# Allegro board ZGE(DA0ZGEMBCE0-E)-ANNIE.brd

Outline 299.69 x 178.8 mm; copper layers: TOP, SGND, IN1, SGND1, IN2, SVCC, SVCC1, IN3, SGND2, IN4, SGND3, BOTTOM. Coordinates in mm from the lower left corner of the outline.
Outline path: 0,55.5 0,51.5 arc(0.44,50.44) 1.5,50 3.2,50 arc(3.55,50.15) 3.7,50.5 3.7,50.9 arc(3.55,51.25) 3.2,51.4 2.7,51.4 arc(2.35,51.55) 2.2,51.9 2.2,53.7 arc(2.43,54.27) 3,54.5 4.9,54.5 arc(5.47,54.27) 5.7,53.7 5.7,51.81 arc(5.72,51.6) 5.78,51.41 6.32,50.19 arc(6.38,50) 6.4,49.79 6.4,39 5.5,39 arc(4.79,38.71) 4.5,38 4.5,9 arc(5.09,7.59) 6.5,7 13.9,7 arc(14.61,7.29) 14.9,8 14.9,10.9 arc(15.19,11.61) 15.9,11.9 38.9,11.9 arc(39.61,11.61) 39.9,10.9 39.9,8 arc(40.19,7.29) 40.9,7 48.9,7 arc(49.61,7.29) 49.9,8 49.9,10.9 arc(50.19,11.61) 50.9,11.9 61.4,11.9 arc(62.11,11.61) 62.4,10.9 62.4,10.4 91.4,10.4 arc(92.11,10.11) 92.4,9.4 92.4,8 arc(92.69,7.29) 93.4,7 278.2,7 arc(279.61,6.41) 280.2,5 280.2,1 arc(280.49,0.29) 281.2,0 296.2,0 arc(297.61,0.59) 298.2,2 298.2,4.85 288.65,4.85 arc(288.15,5.35) 288.65,5.85 288.65,17.55 arc(288.15,18.05) 288.65,18.55 298.2,18.55 298.2,21 299.6,21 299.6,34.7 298.2,34.7 298.2,36 299.69,36 299.69,48 298.2,48 298.2,49.25 296.2,49.25 arc(295.85,49.4) 295.7,49.75 295.7,50.05 arc(295.85,50.4) 296.2,50.55 298.2,50.55 298.2,59.5 arc(297.61,60.91) 296.2,61.5 268.9,61.5 268.9,62.5 224.4,62.5 arc(214.23,63.81) 204.73,67.67 204.73,67.67 arc(201.8,68.29) 199.04,67.12 arc(193.17,67.15) 192.31,72.95 192.42,73.12 arc(193.19,75.97) 192.21,78.75 arc(186.4,90) 184.4,102.5 184.4,174.9 arc(183.81,176.31) 182.4,176.9 131.3,176.9 131.3,177.8 arc(131.01,178.51) 130.3,178.8 105.15,178.8 105.15,176.3 arc(104.35,175.5) 103.55,176.3 103.55,178.8 95.55,178.8 95.55,168.9 arc(96.05,168.4) 95.55,167.9 78.25,167.9 arc(77.75,168.4) 78.25,168.9 78.25,178.8 70.8,178.8 70.8,170.09 arc(70.98,169.66) 70.55,169.84 55.55,169.84 arc(55.12,169.66) 55.3,170.09 55.3,178.8 52.1,178.8 52.1,177.7 41.9,177.7 41.9,176.2 9.9,176.2 9.9,177.7 6.5,177.7 arc(5.09,177.11) 4.5,175.7 4.5,57.5 arc(4.35,57.15) 4,57 1.5,57 arc(0.44,56.56) 0,55.5

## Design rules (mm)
constraint set DEFAULT: min track width 0.14
net group DFP-S3.5(4.5)W6(5)-T13B: nets M_B_DQSN8 M_B_DQSP8
net group DFP-S3.5(4.5)W6(5)-T23B: nets M_A_DQSN8 M_A_DQSP8
net group DFP-S7W5.5-T: nets VGA_XTALIN VGA_XTALOUT
net group DFP-S3.5(4.5)W6(5)-T1B: nets M_B_DQSN0 M_B_DQSN1 M_B_DQSN2 M_B_DQSN3 M_B_DQSN4 M_B_DQSN5 M_B_DQSN6 M_B_DQSN7 M_B_DQSP0 M_B_DQSP1 M_B_DQSP2 M_B_DQSP3 M_B_DQSP4 M_B_DQSP5 M_B_DQSP6 M_B_DQSP7
net group DFP-S3.5(4.5)W6(5)-T2B: nets M_A_DQSN0 M_A_DQSN1 M_A_DQSN2 M_A_DQSN3 M_A_DQSN4 M_A_DQSN5 M_A_DQSN6 M_A_DQSN7 M_A_DQSP0 M_A_DQSP1 M_A_DQSP2 M_A_DQSP3 M_A_DQSP4 M_A_DQSP5 M_A_DQSP6 M_A_DQSP7
net group DFP-S4(4.5)W4.5(3.5)-T2B: nets M_A_DIM0_CLKN0 M_A_DIM0_CLKN1 M_A_DIM0_CLKP0 M_A_DIM0_CLKP1 M_A_DIM1_CLKN0 M_A_DIM1_CLKN1 M_A_DIM1_CLKP0 M_A_DIM1_CLKP1
net group DFP-S4(4.5: nets DP_USB_MUX_SSRXN DP_USB_MUX_SSRXP DP_USB_MUX_SSTXN DP_USB_MUX_SSTXP USB30_RX1+ USB30_RX1+_C USB30_RX1- USB30_RX1-_C USB30_RX2+ USB30_RX2+_C USB30_RX2- USB30_RX2-_C USB30_RX3+ USB30_RX3+_RTO USB30_RX3- USB30_RX3-_RTO USB30_RX4+ USB30_RX4- USB30_TX1+ USB30_TX1+_C USB30_TX1- USB30_TX1-_C USB30_TX2+ USB30_TX2+_C USB30_TX2- USB30_TX2-_C USB30_TX3+ USB30_TX3+_RTI USB30_TX3- USB30_TX3-_RTI USB30_TX4+ USB30_TX4-
net group DFP-S4(4.5: nets VMA_CLK0 VMA_CLK0# VMA_CLK1 VMA_CLK1# VMA_WCK01 VMA_WCK01# VMA_WCK23 VMA_WCK23# VMA_WCK45 VMA_WCK45# VMA_WCK67 VMA_WCK67# VMA_WCKB01 VMA_WCKB01# VMA_WCKB23 VMA_WCKB23# VMA_WCKB45 VMA_WCKB45# VMA_WCKB67 VMA_WCKB67# VMB_CLK0 VMB_CLK0# VMB_CLK1 VMB_CLK1# VMB_WCK01 VMB_WCK01# VMB_WCK23 VMB_WCK23# VMB_WCK45 VMB_WCK45# VMB_WCK67 VMB_WCK67# VMB_WCKB01 VMB_WCKB01# VMB_WCKB23 VMB_WCKB23# VMB_WCKB45 VMB_WCKB45# VMB_WCKB67 VMB_WCKB67# VMC_CLK0 VMC_CLK0# VMC_CLK1 VMC_CLK1# VMC_WCK01 VMC_WCK01# VMC_WCK23 VMC_WCK23# VMC_WCK45 VMC_WCK45# VMC_WCK67 VMC_WCK67# VMC_WCKB01 VMC_WCKB01# VMC_WCKB23 VMC_WCKB23# VMC_WCKB45 VMC_WCKB45# VMC_WCKB67 VMC_WCKB67# VMD_CLK0 VMD_CLK0# VMD_CLK1 VMD_CLK1# VMD_WCK01 VMD_WCK01# VMD_WCK23 VMD_WCK23# VMD_WCK45 VMD_WCK45# VMD_WCK67 VMD_WCK67# VMD_WCKB01 VMD_WCKB01# VMD_WCKB23 VMD_WCKB23# VMD_WCKB45 VMD_WCKB45# VMD_WCKB67 VMD_WCKB67#
net group DFP-S4W4.5(3.5)-T1B: nets M_B_DIM0_CLKN0 M_B_DIM0_CLKN1 M_B_DIM0_CLKP0 M_B_DIM0_CLKP1 M_B_DIM1_CLKN0 M_B_DIM1_CLKN1 M_B_DIM1_CLKP0 M_B_DIM1_CLKP1
net group DFP-S5(3.1)W5.5(3.4)-T1: nets C_PEG_TXN0 C_PEG_TXN1 C_PEG_TXN2 C_PEG_TXN3 C_PEG_TXN4 C_PEG_TXN5 C_PEG_TXN6 C_PEG_TXN7 C_PEG_TXN8 C_PEG_TXN9 C_PEG_TXN10 C_PEG_TXN11 C_PEG_TXN12 C_PEG_TXN13 C_PEG_TXN14 C_PEG_TXN15 C_PEG_TXP0 C_PEG_TXP1 C_PEG_TXP2 C_PEG_TXP3 C_PEG_TXP4 C_PEG_TXP5 C_PEG_TXP6 C_PEG_TXP7 C_PEG_TXP8 C_PEG_TXP9 C_PEG_TXP10 C_PEG_TXP11 C_PEG_TXP12 C_PEG_TXP13 C_PEG_TXP14 C_PEG_TXP15 PEG_TXN0 PEG_TXN1 PEG_TXN2 PEG_TXN3 PEG_TXN4 PEG_TXN5 PEG_TXN6 PEG_TXN7 PEG_TXN8 PEG_TXN9 PEG_TXN10 PEG_TXN11 PEG_TXN12 PEG_TXN13 PEG_TXN14 PEG_TXN15 PEG_TXP0 PEG_TXP1 PEG_TXP2 PEG_TXP3 PEG_TXP4 PEG_TXP5 PEG_TXP6 PEG_TXP7 PEG_TXP8 PEG_TXP9 PEG_TXP10 PEG_TXP11 PEG_TXP12 PEG_TXP13 PEG_TXP14 PEG_TXP15
net group DFP-S5(3.1)W5.5(3.4)-T4: nets DMI_RXN0 DMI_RXN1 DMI_RXN2 DMI_RXN3 DMI_RXP0 DMI_RXP1 DMI_RXP2 DMI_RXP3 DMI_TXN0 DMI_TXN1 DMI_TXN2 DMI_TXN3 DMI_TXP0 DMI_TXP1 DMI_TXP2 DMI_TXP3
net group DFP-S5(3.1: nets CLK_CPU_BCLKN CLK_CPU_BCLKP CLK_DPLL_NSCCLKN CLK_DPLL_NSCCLKP CLK_PCIE_LANN CLK_PCIE_LANP CLK_PCIE_SSD1N CLK_PCIE_SSD1N_R CLK_PCIE_SSD1P CLK_PCIE_SSD1P_R CLK_PCIE_SSD2N CLK_PCIE_SSD2N_R CLK_PCIE_SSD2P CLK_PCIE_SSD2P_R CLK_PCIE_TBTN CLK_PCIE_TBTP CLK_PCIE_WLANN CLK_PCIE_WLANP CLK_VGA_N CLK_VGA_P CNV_WR_CLKN CNV_WR_CLKP CNV_WRXN0 CNV_WRXN1 CNV_WRXP0 CNV_WRXP1 CNV_WT_CLKN CNV_WT_CLKP CNV_WTXN0 CNV_WTXN1 CNV_WTXP0 CNV_WTXP1 CON_UTC_D1N CON_UTC_D1P CON_UTC_D2N CON_UTC_D2P CON_UTC_RX1N CON_UTC_RX1P CON_UTC_RX2N CON_UTC_RX2P CON_UTC_SBU1 CON_UTC_SBU2 CON_UTC_TX1N CON_UTC_TX1P CON_UTC_TX2N CON_UTC_TX2P CPU_PCI_BCLKN CPU_PCI_BCLKP DP_USB_MUX_RX1N DP_USB_MUX_RX1P DP_USB_MUX_RX2N DP_USB_MUX_RX2P DP_USB_MUX_SBU1 DP_USB_MUX_SBU2 DP_USB_MUX_TX1N DP_USB_MUX_TX1P DP_USB_MUX_TX2N DP_USB_MUX_TX2P NV_USB2_D_N NV_USB2_D_P PCIE_RXN9_SSD PCIE_RXN9_SSD_R PCIE_RXN10_SSD PCIE_RXN10_SSD_R PCIE_RXN11_SSD PCIE_RXN11_SSD_R PCIE_RXN12_SSD PCIE_RXN12_SSD_R PCIE_RXN14_LAN PCIE_RXN15_WLAN PCIE_RXN17_TBT PCIE_RXN17_TBT_C PCIE_RXN18_TBT PCIE_RXN18_TBT_C PCIE_RXN19_TBT PCIE_RXN19_TBT_C PCIE_RXN20_TBT PCIE_RXN20_TBT_C PCIE_RXN21_SSD PCIE_RXN21_SSD_R PCIE_RXN22_SSD PCIE_RXN22_SSD_R PCIE_RXN23_SSD PCIE_RXN23_SSD_R PCIE_RXN24_SSD PCIE_RXN24_SSD_R PCIE_RXP9_SSD PCIE_RXP9_SSD_R PCIE_RXP10_SSD PCIE_RXP10_SSD_R PCIE_RXP11_SSD PCIE_RXP11_SSD_R PCIE_RXP12_SSD PCIE_RXP12_SSD_R PCIE_RXP14_LAN PCIE_RXP15_WLAN PCIE_RXP17_TBT PCIE_RXP17_TBT_C PCIE_RXP18_TBT PCIE_RXP18_TBT_C PCIE_RXP19_TBT PCIE_RXP19_TBT_C PCIE_RXP20_TBT PCIE_RXP20_TBT_C PCIE_RXP21_SSD PCIE_RXP21_SSD_R PCIE_RXP22_SSD PCIE_RXP22_SSD_R PCIE_RXP23_SSD PCIE_RXP23_SSD_R PCIE_RXP24_SSD PCIE_RXP24_SSD_R PCIE_TXN9_SSD PCIE_TXN9_SSD_R PCIE_TXN10_SSD PCIE_TXN10_SSD_R PCIE_TXN11_SSD PCIE_TXN11_SSD_R PCIE_TXN12_SSD PCIE_TXN12_SSD_R PCIE_TXN14_LAN PCIE_TXN14_LAN_C PCIE_TXN15_WLAN PCIE_TXN15_WLAN_C PCIE_TXN17_TBT PCIE_TXN17_TBT_C PCIE_TXN18_TBT PCIE_TXN18_TBT_C PCIE_TXN19_TBT PCIE_TXN19_TBT_C PCIE_TXN20_TBT PCIE_TXN20_TBT_C PCIE_TXN21_SSD PCIE_TXN21_SSD_R PCIE_TXN22_SSD PCIE_TXN22_SSD_R PCIE_TXN23_SSD PCIE_TXN23_SSD_R PCIE_TXN24_SSD PCIE_TXN24_SSD_R PCIE_TXP9_SSD PCIE_TXP9_SSD_R PCIE_TXP10_SSD PCIE_TXP10_SSD_R PCIE_TXP11_SSD PCIE_TXP11_SSD_R PCIE_TXP12_SSD PCIE_TXP12_SSD_R PCIE_TXP14_LAN PCIE_TXP14_LAN_C PCIE_TXP15_WLAN PCIE_TXP15_WLAN_C PCIE_TXP17_TBT PCIE_TXP17_TBT_C PCIE_TXP18_TBT PCIE_TXP18_TBT_C PCIE_TXP19_TBT PCIE_TXP19_TBT_C PCIE_TXP20_TBT PCIE_TXP20_TBT_C PCIE_TXP21_SSD PCIE_TXP21_SSD_R PCIE_TXP22_SSD PCIE_TXP22_SSD_R PCIE_TXP23_SSD PCIE_TXP23_SSD_R PCIE_TXP24_SSD PCIE_TXP24_SSD_R SATA_RXN0 SATA_RXN0_CN SATA_RXN_IN SATA_RXN_OUT SATA_RXP0 SATA_RXP0_CN SATA_RXP_IN SATA_RXP_OUT SATA_TXN0 SATA_TXN0_CN SATA_TXN_IN SATA_TXN_OUT SATA_TXP0 SATA_TXP0_CN SATA_TXP_IN SATA_TXP_OUT TBTA_USB2_D_N TBTA_USB2_D_N_T TBTA_USB2_D_P TBTA_USB2_D_P_T USB3O2_MUX_SSTX1N USB3O2_MUX_SSTX1P USB3O2_MUX_SSTX2N USB3O2_MUX_SSTX2P USBP1+ USBP1+_C USBP1- USBP1-_C USBP2+ USBP2+_C USBP2- USBP2-_C USBP3+ USBP3+_C USBP3+_C_R USBP3- USBP3-_C USBP3-_C_R USBP4+ USBP4- USBP5+ USBP5- USBP6+ USBP6+_C USBP6- USBP6-_C USBP7+ USBP7+_R USBP7- USBP7-_R USBP8+ USBP8- USBP14+ USBP14-
net group DFP-S5W5-T1234B: nets 8816ARGDN 8816AVSNS 24780_SRN 24780_SRP FVDDQ_SENSE_I FVDDQ_SENSE_V GPU_ADC_INN GPU_ADC_INP NVVDD_SENSE_I NVVDD_SENSE_V VGPU_CORE_SENSE VSS_GPU_SENSE
net group DFP-S5W5.5(3.4: nets MBCLK1_GPU MBDATA1_GPU USB_I2C_SCL USB_I2C_SDA
net group DFP-S5W5.5-TB: nets PEG_RXN0 PEG_RXN0_C PEG_RXN1 PEG_RXN1_C PEG_RXN2 PEG_RXN2_C PEG_RXN3 PEG_RXN3_C PEG_RXN4 PEG_RXN4_C PEG_RXN5 PEG_RXN5_C PEG_RXN6 PEG_RXN6_C PEG_RXN7 PEG_RXN7_C PEG_RXN8 PEG_RXN8_C PEG_RXN9 PEG_RXN9_C PEG_RXN10 PEG_RXN10_C PEG_RXN11 PEG_RXN11_C PEG_RXN12 PEG_RXN12_C PEG_RXN13 PEG_RXN13_C PEG_RXN14 PEG_RXN14_C PEG_RXN15 PEG_RXN15_C PEG_RXP0 PEG_RXP0_C PEG_RXP1 PEG_RXP1_C PEG_RXP2 PEG_RXP2_C PEG_RXP3 PEG_RXP3_C PEG_RXP4 PEG_RXP4_C PEG_RXP5 PEG_RXP5_C PEG_RXP6 PEG_RXP6_C PEG_RXP7 PEG_RXP7_C PEG_RXP8 PEG_RXP8_C PEG_RXP9 PEG_RXP9_C PEG_RXP10 PEG_RXP10_C PEG_RXP11 PEG_RXP11_C PEG_RXP12 PEG_RXP12_C PEG_RXP13 PEG_RXP13_C PEG_RXP14 PEG_RXP14_C PEG_RXP15 PEG_RXP15_C
net group DFP-S6W30-T1234B: nets C_SPKL+ C_SPKL- F_SPKL+ F_SPKL- F_SPKR+ F_SPKR- N53217580 N53217584 N53218545 N53218614 N56482348 N56482351 N56482420 N56482438 N56545499 N56545754 N56546274 N56546363 R_SPKL+ R_SPKL- R_SPKR+ R_SPKR- S_SPKR+ S_SPKR-
net group DFP-S7(4: nets AUX_SRCN_TBT_C AUX_SRCP_TBT_C C_GPU_TBT_AUXN C_GPU_TBT_AUXP C_GPU_TBT_D0 C_GPU_TBT_D0# C_GPU_TBT_D1 C_GPU_TBT_D1# C_GPU_TBT_D2 C_GPU_TBT_D2# C_GPU_TBT_D3 C_GPU_TBT_D3# C_INT_DP_AUXN C_INT_DP_AUXP C_OUT_DP_TXN0 C_OUT_DP_TXN1 C_OUT_DP_TXN2 C_OUT_DP_TXN3 C_OUT_DP_TXP0 C_OUT_DP_TXP1 C_OUT_DP_TXP2 C_OUT_DP_TXP3 C_OUT_EDP_TXN0 C_OUT_EDP_TXN1 C_OUT_EDP_TXN2 C_OUT_EDP_TXN3 C_OUT_EDP_TXP0 C_OUT_EDP_TXP1 C_OUT_EDP_TXP2 C_OUT_EDP_TXP3 DDI1_TX0_DN DDI1_TX0_DN_C DDI1_TX0_DP DDI1_TX0_DP_C DDI1_TX1_DN DDI1_TX1_DN_C DDI1_TX1_DP DDI1_TX1_DP_C DDI1_TX2_DN DDI1_TX2_DN_C DDI1_TX2_DP DDI1_TX2_DP_C DDI1_TX3_DN DDI1_TX3_DN_C DDI1_TX3_DP DDI1_TX3_DP_C DP_D0 DP_D0# DP_D1 DP_D1# DP_D2 DP_D2# DP_D3 DP_D3# DP_TXN0_R DP_TXN1_R DP_TXN2_R DP_TXN3_R DP_TXP0_R DP_TXP1_R DP_TXP2_R DP_TXP3_R DP_USB_MUX_AUXN DP_USB_MUX_AUXP DP_USB_MUX_ML0N DP_USB_MUX_ML0P DP_USB_MUX_ML1N DP_USB_MUX_ML1P DP_USB_MUX_ML2N DP_USB_MUX_ML2P DP_USB_MUX_ML3N DP_USB_MUX_ML3P EDP_AUX#_C EDP_AUX_C EDP_TXN0_C EDP_TXN1_C EDP_TXN2_C EDP_TXN3_C EDP_TXP0_C EDP_TXP1_C EDP_TXP2_C EDP_TXP3_C GPU_TBT_AUXN GPU_TBT_AUXP GPU_TBT_D0 GPU_TBT_D0# GPU_TBT_D1 GPU_TBT_D1# GPU_TBT_D2 GPU_TBT_D2# GPU_TBT_D3 GPU_TBT_D3# IFPF_AUX+ IFPF_AUX- IFPF_L0+ IFPF_L0- IFPF_L1+ IFPF_L1- IFPF_L2+ IFPF_L2- IFPF_L3+ IFPF_L3- INT_DP_AUXN INT_DP_AUXN_Q INT_DP_AUXP INT_DP_AUXP_Q INT_EDP_AUXN INT_EDP_AUXP INT_EDP_TXN0 INT_EDP_TXN0_R INT_EDP_TXN1 INT_EDP_TXN1_R INT_EDP_TXN2 INT_EDP_TXN2_R INT_EDP_TXN3 INT_EDP_TXN3_R INT_EDP_TXP0 INT_EDP_TXP0_R INT_EDP_TXP1 INT_EDP_TXP1_R INT_EDP_TXP2 INT_EDP_TXP2_R INT_EDP_TXP3 INT_EDP_TXP3_R OUT_DP_TXN0 OUT_DP_TXN1 OUT_DP_TXN2 OUT_DP_TXN3 OUT_DP_TXP0 OUT_DP_TXP1 OUT_DP_TXP2 OUT_DP_TXP3 TBTA_AUX_N TBTA_AUX_P TBTA_DPSRC_AUX_N TBTA_DPSRC_AUX_P TBTA_LSRX TBTA_LSTX TBTA_SBU1 TBTA_SBU2
net group DFP-S7W5.5-TB: nets TBTA_CA2HD_0_N TBTA_CA2HD_0_P TBTA_CA2HD_1_N TBTA_CA2HD_1_P TBTA_HD2CA_0_N TBTA_HD2CA_0_P TBTA_HD2CA_1_N TBTA_HD2CA_1_P TBTA_TX0_N TBTA_TX0_P TBTA_TX1_N TBTA_TX1_P
net group DFP-S8(5: nets GPU_USB_L0+ GPU_USB_L0- GPU_USB_L1+ GPU_USB_L1- USB3_RT_RX1N USB3_RT_RX1P USB3_RT_SSRXN USB3_RT_SSRXP USB3_RT_SSTXN USB3_RT_SSTXP USB3_RT_TX1N USB3_RT_TX1P USB3O2_MUX_SSRXN USB3O2_MUX_SSRXP USB3O2_MUX_SSTXN USB3O2_MUX_SSTXP
net group DFP-S11(6: nets C_TX0_HDMI+ C_TX0_HDMI- C_TX1_HDMI+ C_TX1_HDMI- C_TX2_HDMI+ C_TX2_HDMI- C_TXC_HDMI+ C_TXC_HDMI- GPU_CLK GPU_CLK# GPU_CLK#_C GPU_CLK_C GPU_D0 GPU_D0# GPU_D0#_C GPU_D0_C GPU_D1 GPU_D1# GPU_D1#_C GPU_D1_C GPU_D2 GPU_D2# GPU_D2#_C GPU_D2_C TX0_HDMI+ TX0_HDMI- TX1_HDMI+ TX1_HDMI- TX2_HDMI+ TX2_HDMI- TXC_HDMI+ TXC_HDMI- USB30_RX1+_R USB30_RX1+_RT USB30_RX1-_R USB30_RX1-_RT USB30_RX2+_R USB30_RX2+_RT USB30_RX2-_R USB30_RX2-_RT USB30_RX3+_R USB30_RX3+_RTI USB30_RX3-_R USB30_RX3-_RTI USB30_TX1+_R USB30_TX1+_RT USB30_TX1-_R USB30_TX1-_RT USB30_TX2+_R USB30_TX2+_RT USB30_TX2-_R USB30_TX2-_RT USB30_TX3+_C USB30_TX3+_R USB30_TX3+_RTO USB30_TX3-_C USB30_TX3-_R USB30_TX3-_RTO
net group W4-TB: nets USB2_COMP
net group W5-T1234B: nets FB_CAL_PD_VDDQ FB_CAL_PU_GND FB_CAL_TERM_GND
net group W5.5(3.4: nets 2ND_MBCLK 2ND_MBDATA 3ND_MBCLK 3ND_MBCLK_C 3ND_MBDATA 3ND_MBDATA_C 81215_ALERT 81215_SCLK 81215_SDIO ACZ_BCLK ACZ_RST# ACZ_SDIN0_R ACZ_SDO ACZ_SYNC AUD_AZACPU_SCLK AUD_AZACPU_SCLK_R AUD_AZACPU_SDI AUD_AZACPU_SDI_R AUD_AZACPU_SDO AUD_AZACPU_SDO_R BL# BL_ON BLON_EN BLONCON CL_CLK CL_DATA CLK_PCI_EC CLK_PCI_EC_R CLK_PCI_LPC CLK_PCI_LPC_C CLK_PCI_LPC_R CLKIN_XTAL CNV_BRI_DT CNV_BRI_RSP CNV_RGI_DT CNV_RGI_RSP CPU_PLTRST# CPU_PLTRST#R DDCCLK_NOR DDCCLK_NOR-1 DDCDATA_NOR DDCDATA_NOR-1 DDR4_SUSON_2V5 DDR_DRAMRST# DDR_PG_CNTL DDR_VTTT_PG_CTRL DGPU_HOLD_RST# DGPU_OPP# DGPU_OPP#_PROCHOT# DMIC_CLK DMIC_CLK_C DMIC_DAT DMIC_DATA_C DP_HPD DP_HPD_PCH DP_HPD_PCH_R DPWROK_R EC_PECI EC_PECR_R EC_PWROK EC_PWROK_R EDP_HPD_GPU EDP_HPD_R EDP_HPD_RR EDP_VDD_EN ESPI_EC_IO0 ESPI_EC_IO1 ESPI_EC_IO2 ESPI_EC_IO3 FAN1_PWM FAN1_PWM_Q FAN1_RPM FAN2_PWM FAN2_PWM_Q FAN2_RPM FRM_LCK# FRM_LCK#_PANEL GFX_SCL GFX_SDA GPIO27_IFPC_HPD GPIO27_IFPE_HPD_Q GPU_DDCCLK GPU_DDCDATA GPU_IFPB_I2C_SCL GPU_IFPB_I2C_SDA GPU_THROTTING# GPU_USB_I2C_SCL GPU_USB_I2C_SDA GPUT_CLK GPUT_DATA H_CPU_SVIDALRT# H_CPU_SVIDDAT H_PROCHOT# H_PROCHOT#_CPU H_TCK H_TDI H_TDO H_TMS H_TRST# H_VCCST_PWRGD HDMI_HPD HDMI_HPD_DC HDMI_HPD_PCH HDMI_HPD_PCH_R HDMI_SCLK HDMI_SDATA HOLLD#_7 HP_JD#_EC HPD_IFPD HWPG HWPG_1.8VS5 HWPG_1VS5 HWPG_2.5V HWPG_VDDR I2C0_SCL I2C0_SDA I2C1_SCL I2C1_SDA I2C_TP_SCL_R I2C_TP_SDA_R IFPB_I2C_SCL IFPB_I2C_SDA IMVP_PWRGD LCD_BL_PWM LCD_BLEN LCD_VDD LID# LID#_EC_L LPC_LAD0 LPC_LAD0_C LPC_LAD1 LPC_LAD1_C LPC_LAD2 LPC_LAD2_C LPC_LAD3 LPC_LAD3_C LPC_LFRAME# LPC_LFRAME#_C MAINON MB_THRMTRIP# MBCLK MBDATA MODEM_CLKREQ N17086720 N49317148 N53212868 N53212870 N53213208 N53256180 N53256182 N56382763 N56382839 NGFF1_RST# NGFF2_RST# PCH_AZ_CODEC_BITCLK PCH_AZ_CODEC_RST# PCH_AZ_CODEC_SDIN0 PCH_AZ_CODEC_SDOUT PCH_AZ_CODEC_SYNC PCH_BRIGHT PCH_PECI PCH_PWROK PCH_RSMRST# PCH_SMBCLK PCH_SMBDATA PCH_SPI1_CLK PCH_SPI1_CLK_L PCH_SPI1_SI PCH_SPI1_SI_L PCH_SPI1_SO PCH_SPI1_SO_L PCH_SPI_CLK_EC PCH_SPI_CS0# PCH_SPI_IO2 PCH_SPI_IO3 PCH_SPI_SI_EC PCH_SPI_SO_EC PCI_PLTRST# PCIE_CLKREQ_LAN# PCIE_CLKREQ_NGFF1# PCIE_CLKREQ_NGFF2# PCIE_CLKREQ_TBT# PCIE_CLKREQ_TBT#_C PCIE_CLKREQ_VGA# PCIE_CLKREQ_WLAN# PECI PEGX_RST# PEX_CLKREQ PLTRST# PLTRST#_EC PM_THRMTRIP# PM_THRMTRIP#_L PPC_I2CM_SCL_C PPC_I2CM_SDA_C PPC_I2CS_SCL_C PPC_I2CS_SDA_C PROCHOT_EC PROCPWRGD ROM_CS ROM_CS_R ROM_SCLK ROM_SCLK_R ROM_SI ROM_SI_R ROM_SO RSMRST# RTC_RST# S5_ON SLP_A# SLP_A#_L SLP_S3#_L SLP_S4#_L SMB_ME1_CLK SMB_ME1_DAT SMB_PCH_CLK SMB_PCH_DAT SPI1_IO2 SPI1_IO3 SPI_CS0#_UR_ME SPI_TPM_CS# SPI_TPM_CS#_L SRTC_RST# SUSB# SUSC# SUSON SYS_HWPG SYS_PWROK TBT_EE_CLK TBT_EE_CS_N TBT_EE_DI TBT_EE_DO TBT_EE_WP_N TBT_I2C_SCL1 TBT_I2C_SDA1 TBT_MAINON TBT_SPI_HOLD# TI_TBT_EE_CLK TI_TBT_EE_CS_N TI_TBT_EE_DI TI_TBT_EE_DO TI_TBT_EE_WP_N TI_TBT_SPI_HOLD# TPCLK TPDATA TPM_SCS# ULT_EDP_HPD_Q USB3_RT_SCL USB3_RT_SDA USB3O2_MUX_CFG_SCL USB3O2_MUX_CFG_SDA USB_I2C_SCL_3V3OR1V8 USB_I2C_SDA_3V3OR1V8 VCCST_PWRGD VR_SVID_ALERT# VR_SVID_CLK VR_SVID_CLK_R VR_SVID_DATA VRON WLAN_CLKREQ# WLAN_RST# WP#_3
net group W5.5-B: nets TBT1_PCIE_RBIAS TBT_RBIAS TBT_RSENSE
net group W5.5-T: nets DP_USB_MUX_XTAL_I DP_USB_MUX_XTAL_O DP_USB_MUX_XTAL_O_R RTC_X1 RTC_X2 TBT_XTL25_IN TBT_XTL25_OUT USB3_RT_XTAL_I USB3_RT_XTAL_O USB3_RT_XTAL_O_R VGA_XTALOUT_R XTALOUT_RC XTALSSIN
net group W5.5-TB: nets XTAL24_IN XTAL24_IN_L XTAL24_OUT XTAL24_OUT_L XTALOUTBUFF
net group W6.5(4: nets FBA_CMD0 FBA_CMD1 FBA_CMD2 FBA_CMD3 FBA_CMD4 FBA_CMD5 FBA_CMD6 FBA_CMD7 FBA_CMD8 FBA_CMD9 FBA_CMD10 FBA_CMD11 FBA_CMD12 FBA_CMD13 FBA_CMD14 FBA_CMD15 FBA_CMD16 FBA_CMD17 FBA_CMD18 FBA_CMD19 FBA_CMD20 FBA_CMD21 FBA_CMD22 FBA_CMD23 FBA_CMD24 FBA_CMD25 FBA_CMD26 FBA_CMD27 FBA_CMD28 FBA_CMD29 FBA_CMD30 FBA_CMD31 FBA_CMD32 FBA_CMD33 FBA_DEBUG0 FBA_DEBUG1 FBB_CMD0 FBB_CMD1 FBB_CMD2 FBB_CMD3 FBB_CMD4 FBB_CMD5 FBB_CMD6 FBB_CMD7 FBB_CMD8 FBB_CMD9 FBB_CMD10 FBB_CMD11 FBB_CMD12 FBB_CMD13 FBB_CMD14 FBB_CMD15 FBB_CMD16 FBB_CMD17 FBB_CMD18 FBB_CMD19 FBB_CMD20 FBB_CMD21 FBB_CMD22 FBB_CMD23 FBB_CMD24 FBB_CMD25 FBB_CMD26 FBB_CMD27 FBB_CMD28 FBB_CMD29 FBB_CMD30 FBB_CMD31 FBB_CMD32 FBB_CMD33 FBB_DEBUG0 FBB_DEBUG1 FBC_CMD0 FBC_CMD1 FBC_CMD2 FBC_CMD3 FBC_CMD4 FBC_CMD5 FBC_CMD6 FBC_CMD7 FBC_CMD8 FBC_CMD9 FBC_CMD10 FBC_CMD11 FBC_CMD12 FBC_CMD13 FBC_CMD14 FBC_CMD15 FBC_CMD16 FBC_CMD17 FBC_CMD18 FBC_CMD19 FBC_CMD20 FBC_CMD21 FBC_CMD22 FBC_CMD23 FBC_CMD24 FBC_CMD25 FBC_CMD26 FBC_CMD27 FBC_CMD28 FBC_CMD29 FBC_CMD30 FBC_CMD31 FBC_CMD32 FBC_CMD33 FBC_DEBUG0 FBC_DEBUG1 FBD_CMD0 FBD_CMD1 FBD_CMD2 FBD_CMD3 FBD_CMD4 FBD_CMD5 FBD_CMD6 FBD_CMD7 FBD_CMD8 FBD_CMD9 FBD_CMD10 FBD_CMD11 FBD_CMD12 FBD_CMD13 FBD_CMD14 FBD_CMD15 FBD_CMD16 FBD_CMD17 FBD_CMD18 FBD_CMD19 FBD_CMD20 FBD_CMD21 FBD_CMD22 FBD_CMD23 FBD_CMD24 FBD_CMD25 FBD_CMD26 FBD_CMD27 FBD_CMD28 FBD_CMD29 FBD_CMD30 FBD_CMD31 FBD_CMD32 FBD_CMD33 FBD_DEBUG0 FBD_DEBUG1
net group W7.5(4.5)-T1B: nets M_B_DQ0 M_B_DQ1 M_B_DQ2 M_B_DQ3 M_B_DQ4 M_B_DQ5 M_B_DQ6 M_B_DQ7 M_B_DQ8 M_B_DQ9 M_B_DQ10 M_B_DQ11 M_B_DQ12 M_B_DQ13 M_B_DQ14 M_B_DQ15 M_B_DQ16 M_B_DQ17 M_B_DQ18 M_B_DQ19 M_B_DQ20 M_B_DQ21 M_B_DQ22 M_B_DQ23 M_B_DQ24 M_B_DQ25 M_B_DQ26 M_B_DQ27 M_B_DQ28 M_B_DQ29 M_B_DQ30 M_B_DQ31 M_B_DQ32 M_B_DQ33 M_B_DQ34 M_B_DQ35 M_B_DQ36 M_B_DQ37 M_B_DQ38 M_B_DQ39 M_B_DQ40 M_B_DQ41 M_B_DQ42 M_B_DQ43 M_B_DQ44 M_B_DQ45 M_B_DQ46 M_B_DQ47 M_B_DQ48 M_B_DQ49 M_B_DQ50 M_B_DQ51 M_B_DQ52 M_B_DQ53 M_B_DQ54 M_B_DQ55 M_B_DQ56 M_B_DQ57 M_B_DQ58 M_B_DQ59 M_B_DQ60 M_B_DQ61 M_B_DQ62 M_B_DQ63
net group W7.5(4.5)-T13B: nets M_B_CB0 M_B_CB1 M_B_CB2 M_B_CB3 M_B_CB4 M_B_CB5 M_B_CB6 M_B_CB7
net group W7.5(5)-T2B: nets M_A_DQ0 M_A_DQ1 M_A_DQ2 M_A_DQ3 M_A_DQ4 M_A_DQ5 M_A_DQ6 M_A_DQ7 M_A_DQ8 M_A_DQ9 M_A_DQ10 M_A_DQ11 M_A_DQ12 M_A_DQ13 M_A_DQ14 M_A_DQ15 M_A_DQ16 M_A_DQ17 M_A_DQ18 M_A_DQ19 M_A_DQ20 M_A_DQ21 M_A_DQ22 M_A_DQ23 M_A_DQ24 M_A_DQ25 M_A_DQ26 M_A_DQ27 M_A_DQ28 M_A_DQ29 M_A_DQ30 M_A_DQ31 M_A_DQ32 M_A_DQ33 M_A_DQ34 M_A_DQ35 M_A_DQ36 M_A_DQ37 M_A_DQ38 M_A_DQ39 M_A_DQ40 M_A_DQ41 M_A_DQ42 M_A_DQ43 M_A_DQ44 M_A_DQ45 M_A_DQ46 M_A_DQ47 M_A_DQ48 M_A_DQ49 M_A_DQ50 M_A_DQ51 M_A_DQ52 M_A_DQ53 M_A_DQ54 M_A_DQ55 M_A_DQ56 M_A_DQ57 M_A_DQ58 M_A_DQ59 M_A_DQ60 M_A_DQ61 M_A_DQ62 M_A_DQ63
net group W7.5(5)-T23B: nets M_A_CB0 M_A_CB1 M_A_CB2 M_A_CB3 M_A_CB4 M_A_CB5 M_A_CB6 M_A_CB7
net group W8-T1234B: nets N53212908 N53213106 VCCSA_VCCSENSE VCCSA_VSSSENSE
net group W8.5(5)-T1B: nets M_B_CKE0 M_B_CKE1 M_B_CKE2 M_B_CKE3 M_B_CS#0 M_B_CS#1 M_B_CS#2 M_B_CS#3 M_B_ODT0 M_B_ODT1 M_B_ODT2 M_B_ODT3
net group W8.5(5: nets FBA_DBI0 FBA_DBI1 FBA_DBI2 FBA_DBI3 FBA_DBI4 FBA_DBI5 FBA_DBI6 FBA_DBI7 FBA_EDC0 FBA_EDC1 FBA_EDC2 FBA_EDC3 FBA_EDC4 FBA_EDC5 FBA_EDC6 FBA_EDC7 FBB_DBI0 FBB_DBI1 FBB_DBI2 FBB_DBI3 FBB_DBI4 FBB_DBI5 FBB_DBI6 FBB_DBI7 FBB_EDC0 FBB_EDC1 FBB_EDC2 FBB_EDC3 FBB_EDC4 FBB_EDC5 FBB_EDC6 FBB_EDC7 FBC_DBI0 FBC_DBI1 FBC_DBI2 FBC_DBI3 FBC_DBI4 FBC_DBI5 FBC_DBI6 FBC_DBI7 FBC_EDC0 FBC_EDC1 FBC_EDC2 FBC_EDC3 FBC_EDC4 FBC_EDC5 FBC_EDC6 FBC_EDC7 FBD_DBI0 FBD_DBI1 FBD_DBI2 FBD_DBI3 FBD_DBI4 FBD_DBI5 FBD_DBI6 FBD_DBI7 FBD_EDC0 FBD_EDC1 FBD_EDC2 FBD_EDC3 FBD_EDC4 FBD_EDC5 FBD_EDC6 FBD_EDC7 VMA_DQ0 VMA_DQ1 VMA_DQ2 VMA_DQ3 VMA_DQ4 VMA_DQ5 VMA_DQ6 VMA_DQ7 VMA_DQ8 VMA_DQ9 VMA_DQ10 VMA_DQ11 VMA_DQ12 VMA_DQ13 VMA_DQ14 VMA_DQ15 VMA_DQ16 VMA_DQ17 VMA_DQ18 VMA_DQ19 VMA_DQ20 VMA_DQ21 VMA_DQ22 VMA_DQ23 VMA_DQ24 VMA_DQ25 VMA_DQ26 VMA_DQ27 VMA_DQ28 VMA_DQ29 VMA_DQ30 VMA_DQ31 VMA_DQ32 VMA_DQ33 VMA_DQ34 VMA_DQ35 VMA_DQ36 VMA_DQ37 VMA_DQ38 VMA_DQ39 VMA_DQ40 VMA_DQ41 VMA_DQ42 VMA_DQ43 VMA_DQ44 VMA_DQ45 VMA_DQ46 VMA_DQ47 VMA_DQ48 VMA_DQ49 VMA_DQ50 VMA_DQ51 VMA_DQ52 VMA_DQ53 VMA_DQ54 VMA_DQ55 VMA_DQ56 VMA_DQ57 VMA_DQ58 VMA_DQ59 VMA_DQ60 VMA_DQ61 VMA_DQ62 VMA_DQ63 VMB_DQ0 VMB_DQ1 VMB_DQ2 VMB_DQ3 VMB_DQ4 VMB_DQ5 VMB_DQ6 VMB_DQ7 VMB_DQ8 VMB_DQ9 VMB_DQ10 VMB_DQ11 VMB_DQ12 VMB_DQ13 VMB_DQ14 VMB_DQ15 VMB_DQ16 VMB_DQ17 VMB_DQ18 VMB_DQ19 VMB_DQ20 VMB_DQ21 VMB_DQ22 VMB_DQ23 VMB_DQ24 VMB_DQ25 VMB_DQ26 VMB_DQ27 VMB_DQ28 VMB_DQ29 VMB_DQ30 VMB_DQ31 VMB_DQ32 VMB_DQ33 VMB_DQ34 VMB_DQ35 VMB_DQ36 VMB_DQ37 VMB_DQ38 VMB_DQ39 VMB_DQ40 VMB_DQ41 VMB_DQ42 VMB_DQ43 VMB_DQ44 VMB_DQ45 VMB_DQ46 VMB_DQ47 VMB_DQ48 VMB_DQ49 VMB_DQ50 VMB_DQ51 VMB_DQ52 VMB_DQ53 VMB_DQ54 VMB_DQ55 VMB_DQ56 VMB_DQ57 VMB_DQ58 VMB_DQ59 VMB_DQ60 VMB_DQ61 VMB_DQ62 VMB_DQ63 VMC_DQ0 VMC_DQ1 VMC_DQ2 VMC_DQ3 VMC_DQ4 VMC_DQ5 VMC_DQ6 VMC_DQ7 VMC_DQ8 VMC_DQ9 VMC_DQ10 VMC_DQ11 VMC_DQ12 VMC_DQ13 VMC_DQ14 VMC_DQ15 VMC_DQ16 VMC_DQ17 VMC_DQ18 VMC_DQ19 VMC_DQ20 VMC_DQ21 VMC_DQ22 VMC_DQ23 VMC_DQ24 VMC_DQ25 VMC_DQ26 VMC_DQ27 VMC_DQ28 VMC_DQ29 VMC_DQ30 VMC_DQ31 VMC_DQ32 VMC_DQ33 VMC_DQ34 VMC_DQ35 VMC_DQ36 VMC_DQ37 VMC_DQ38 VMC_DQ39 VMC_DQ40 VMC_DQ41 VMC_DQ42 VMC_DQ43 VMC_DQ44 VMC_DQ45 VMC_DQ46 VMC_DQ47 VMC_DQ48 VMC_DQ49 VMC_DQ50 VMC_DQ51 VMC_DQ52 VMC_DQ53 VMC_DQ54 VMC_DQ55 VMC_DQ56 VMC_DQ57 VMC_DQ58 VMC_DQ59 VMC_DQ60 VMC_DQ61 VMC_DQ62 VMC_DQ63 VMD_DQ0 VMD_DQ1 VMD_DQ2 VMD_DQ3 VMD_DQ4 VMD_DQ5 VMD_DQ6 VMD_DQ7 VMD_DQ8 VMD_DQ9 VMD_DQ10 VMD_DQ11 VMD_DQ12 VMD_DQ13 VMD_DQ14 VMD_DQ15 VMD_DQ16 VMD_DQ17 VMD_DQ18 VMD_DQ19 VMD_DQ20 VMD_DQ21 VMD_DQ22 VMD_DQ23 VMD_DQ24 VMD_DQ25 VMD_DQ26 VMD_DQ27 VMD_DQ28 VMD_DQ29 VMD_DQ30 VMD_DQ31 VMD_DQ32 VMD_DQ33 VMD_DQ34 VMD_DQ35 VMD_DQ36 VMD_DQ37 VMD_DQ38 VMD_DQ39 VMD_DQ40 VMD_DQ41 VMD_DQ42 VMD_DQ43 VMD_DQ44 VMD_DQ45 VMD_DQ46 VMD_DQ47 VMD_DQ48 VMD_DQ49 VMD_DQ50 VMD_DQ51 VMD_DQ52 VMD_DQ53 VMD_DQ54 VMD_DQ55 VMD_DQ56 VMD_DQ57 VMD_DQ58 VMD_DQ59 VMD_DQ60 VMD_DQ61 VMD_DQ62 VMD_DQ63
net group W8.5(5.5)-T2B: nets M_A_CKE0 M_A_CKE1 M_A_CKE2 M_A_CKE3 M_A_CS#0 M_A_CS#1 M_A_CS#2 M_A_CS#3 M_A_ODT0 M_A_ODT1 M_A_ODT2 M_A_ODT3
net group W10-T1234B: nets 5V_VCONN +3V_EC +VCC3P3_LC +VCC3P3_S0 +VCC3P3_SX FBVDDQ_SENSE HP-L1 HP-R1 MCR_LED_PWR_1 MCR_LED_PWR_2 MCR_LED_PWR_3 MCR_LED_PWR_P MCR_LED_PWR_T MIC1-L MIC1-R MIC1-VREFO-L MIC1-VREFO-R N53212830 N53213083 N53369186 PPC_VCCD_C PPC_VCON_5V PW_VCC3_ANA_PCIE PW_VCC3_ANA_USB VCC3V3_FLASH
net group W10-TB: nets CFG_RCOMP CNV_RCOMP EDP_RCOMP PEG_COMP
net group W10.5(6)-T1B: nets DDR1_ALERT# DDR1_PAR DDRB_ACT# M_B_A0 M_B_A1 M_B_A2 M_B_A3 M_B_A4 M_B_A5 M_B_A6 M_B_A7 M_B_A8 M_B_A9 M_B_A10 M_B_A11 M_B_A12 M_B_A13 M_B_A14 M_B_A15 M_B_A16 M_B_BG#0 M_B_BG#1 M_B_BS#0 M_B_BS#1
net group W10.5(7)-T2B: nets DDR0_ALERT# DDR0_PAR DDRA_ACT# M_A_A0 M_A_A1 M_A_A2 M_A_A3 M_A_A4 M_A_A5 M_A_A6 M_A_A7 M_A_A8 M_A_A9 M_A_A10 M_A_A11 M_A_A12 M_A_A13 M_A_A14 M_A_A15 M_A_A16 M_A_BG#0 M_A_BG#1 M_A_BS#0 M_A_BS#1
net group W12-T1234B: nets +3V3PD +3V3PD-1 +3V_VCCSPI +3VPCU_EC +3VPCU_ECPLL +V3.3DX_ADO +VCCA_BCLK +VCCPGPPA +VCCPRIM_MPHY +VCCST FBA_PLL_AVDD PEX_PLL_HVDD VCC0P9_LVR
net group W15-T1234B: nets 1V8_ANX +3V_LDO_EC +3V_U3 +VDD33 +VDD_DCI AVDD09 CEN_SPK DP_USB_MUX_VDDIO FRONT_L_SPK FRONT_R_SPK N53214493 N53214499 N53214581 N53214870 N53217570 N53217572 N53217576 N53217761 N53218533 N53218537 N53218575 N53218722 N56481431 N56481770 N56543890 N56544006 N56544277 N56544490 PPC_CC1_6 PPC_CC2_4 SM_RCOMP_0 SM_RCOMP_1 SM_RCOMP_2 SURR_L_SPK SURR_R_SPK TBTA_CC1 TBTA_CC2 TPM_VDD USB3_RT_0V9 USB3_RT_VIN USB3O2_MUX_AVDD33 USB_CC1 USB_CC2 VCC0P9_USB VSTBY_FSPI WOOFER_SPK
net group W16-TB: nets FB_VREF_PROBE
net group W20-T1234B: nets +1.2V_U3 +1.8V_DEEP_SUS +2.5VSUS +3V_AR +3V_DP +3V_DVDD +3V_DVDD_IO +3V_EDP +3V_HDMI +3V_RTC +3V_RTC_0 +3V_RTC_1 +3V_SSD1 +3V_SSD2 +3V_TYPEC_DP1 +5V_HDD +5V_HDMIC +5V_KB_M +5V_MCU +5VA +12V_FAN +12V_FAN1 +12V_FAN2 +SMDDR_VREF_CHA_DIMM0_R +SMDDR_VREF_CHB_DIMM0_R +TPVDD +USBPWR +USBPWR3 +VCCA_XTAL +VCCAMPHYPLL +VCCAPLL_1 +VCCAPLL_2 +VCCDPHY +VCCDSW_1.05V +VCCDUSB +VCCPLL +VCCPLL_OC +VCCSTG +VDD12 +VDDIO +VREFCA_CHA_DIMM +VREFCA_CHB_DIMM +WL_VDD CCD_PWR CORE_PLLVDD DP_USB_MUX_0V9 DP_USB_MUX_AVDD09 DP_USB_MUX_VIN DP_USB_MUX_VX FBA_VREFC GLS_LED_EN_B GLS_LED_EN_G GLS_LED_EN_R LANVCC LCDVCC MCR_LED_EN_B MCR_LED_EN_G MCR_LED_EN_R MCR_LED_T_EN_B MCR_LED_T_EN_G MCR_LED_T_EN_R MIC_VCC N19453152 N33880211 N56085154 N56085203 N56197477 SMDDR_VREF_CA SMDDR_VREF_DQ1_M3 TBTA_VBUS_L TP_LED_EN_W TP_LED_PWR USB3_RT_VX USBC_VBUS VCC0P9_CIO VCC0P9_DP VCC0P9_PCIE VCC0P9_SVR VCC0P9_SVR_IND VCCPHVLDO_1P8
net group W25-T1234B: nets GLS_LED_PWR
net group W30-T1234B: nets N53638085

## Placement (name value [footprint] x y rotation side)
C1  0.1u/16V_4  [C0402]  48.41 165.65 270 top
C2  0.01u/50V_4  [C0402]  49.42 165.65 270 top
C3  0.01u/50V_4  [C0402]  51.45 165.65 270 top
C4  0.1u/16V_4  [C0402]  52.47 165.65 270 top
C5  0.1u/16V_4  [C0402]  53.49 165.65 270 top
C8  0.01u/50V_4  [C0402]  55.01 164.51 180 top
C9  220p/50V_4  [C0402]  70 164.51 90 top
C10  0.1u/10V_2  [C0201]  16.15 164.25 90 top
C11  0.1u/16V_4  [C0402]  49.29 164.05 0 top
C12  0.1u/16V_4  [C0402]  68.93 163.64 270 top
C13  0.1u/16V_4  [C0402]  55.01 163.49 180 top
C14  1u/6.3V_4  [C0402]  70.63 163.06 180 top
C15  0.1u/16V_4  [C0402]  49.29 163.03 0 top
C16  0.1u/16V_4  [C0402]  55.01 162.47 180 top
C17  0.01u/50V_4  [C0402]  49.29 162.02 0 top
C18  0.1u/10V_2  [C0201]  82.06 161.23 270 top
C19  10u/6.3V_4  [C0402_2]  80.92 160.98 90 top
C20  10u/6.3V_4  [C0402_2]  49.29 160.82 180 top
C21  0.01u/50V_4  [C0402]  51.83 160.49 90 top
C22  0.1u/16V_4  [C0402]  52.85 160.49 90 top
C23  *1u/6.3V_4  [C0402]  66.66 160.8 90 top
C24  0.1u/10V_2  [C0201]  87.75 160.07 270 top
C25  0.1u/10V_2  [C0201]  88.9 160.07 270 top
C26  0.1u/10V_2  [C0201]  92.27 160.06 270 top
C27  0.1u/10V_2  [C0201]  93.49 160.06 270 top
C28  0.1u/10V_2  [C0201]  94.56 160.04 270 top
C29  0.1u/10V_2  [C0201]  95.78 160.04 270 top
C30  0.1u/10V_2  [C0201]  89.93 160.02 270 top
C31  0.1u/10V_2  [C0201]  91.1 160.02 270 top
C32  0.1u/10V_2  [C0201]  95.01 154.35 90 top
C33  0.1u/10V_2  [C0201]  89.43 153.79 0 top
C34  *1u/6.3V_2  [C0201]  88.99 152.77 270 top
C35  0.1u/10V_2  [C0201]  88.64 149.48 270 top
C36  *1u/10V_2  [C0201]  127.98 134.68 0 top
C37  *1u/10V_2  [C0201]  129 134.68 180 top
C38  *1u/10V_2  [C0201]  130.52 134.68 0 top
C39  *1u/10V_2  [C0201]  131.54 134.68 180 top
C40  *1u/10V_2  [C0201]  132.81 134.68 0 top
C41  *1u/10V_2  [C0201]  133.82 134.68 180 top
C42  *1u/10V_2  [C0201]  135.35 134.68 0 top
C43  *1u/10V_2  [C0201]  136.36 134.68 180 top
C44  *1u/10V_2  [C0201]  141.62 134.66 180 top
C45  *1u/10V_2  [C0201]  142.89 134.66 0 top
C46  *1u/10V_2  [C0201]  144.04 134.66 180 top
C47  *1u/10V_2  [C0201]  145.05 134.66 180 top
C48  *0.1u/16V_4  [C0402]  167.91 134.66 180 top
C49  1000p/50V_4  [C0402]  177.4 134.19 90 top
C50  0.1u/10V_2  [C0201]  175.76 134.2 270 top
C51  0.1u/10V_2  [C0201]  174.94 131.86 270 top
C52  1000p/50V_4  [C0402]  175.79 132.38 90 top
C53  220p/50V_4  [C0402]  177.69 129.58 180 top
C54  220p/50V_4  [C0402]  177.69 128.62 180 top
C55  180p/50V_4  [C0402]  167.9 128.08 0 top
C56  220p/50V_4  [C0402]  163.85 127.68 180 top
C57  0.22u/6.3V_2  [C0201]  114.27 127.19 0 top
C58  0.22u/6.3V_2  [C0201]  114.27 126.43 0 top
C59  0.22u/6.3V_2  [C0201]  113.25 125.92 0 top
C60  0.1u/16V_4  [C0402]  168.73 125.41 90 top
C61  0.22u/6.3V_2  [C0201]  113.25 125.16 0 top
C62  33p/50V_4  [C0402]  177.44 124.76 90 top
C63  0.22u/6.3V_2  [C0201]  114.25 124.65 0 top
C64  0.22u/6.3V_2  [C0201]  114.25 123.89 0 top
C65  0.22u/6.3V_2  [C0201]  113.25 123.38 0 top
C66  33p/50V_4  [C0402]  177.44 122.85 270 top
C67  0.22u/6.3V_2  [C0201]  113.25 122.62 0 top
C68  0.22u/6.3V_2  [C0201]  114.27 122.11 0 top
C69  0.22u/6.3V_2  [C0201]  114.27 121.35 0 top
C70  0.22u/6.3V_2  [C0201]  113.25 120.84 0 top
C71  0.22u/6.3V_2  [C0201]  113.25 120.08 0 top
C72  0.22u/6.3V_2  [C0201]  114.27 119.57 0 top
C73  0.22u/6.3V_2  [C0201]  114.27 118.81 0 top
C74  0.22u/6.3V_2  [C0201]  113.25 118.17 0 top
C75  0.22u/6.3V_2  [C0201]  113.25 117.41 0 top
C76  0.22u/6.3V_2  [C0201]  114.27 116.9 0 top
C77  0.22u/6.3V_2  [C0201]  114.27 116.14 0 top
C78  0.22u/6.3V_2  [C0201]  113.25 115.63 0 top
C79  0.22u/6.3V_2  [C0201]  113.25 114.87 0 top
C80  0.22u/6.3V_2  [C0201]  114.27 114.36 0 top
C81  0.22u/6.3V_2  [C0201]  114.27 113.6 0 top
C82  0.22u/6.3V_2  [C0201]  113.25 113.09 0 top
C83  0.22u/6.3V_2  [C0201]  113.25 112.33 0 top
C84  0.22u/6.3V_2  [C0201]  114.27 111.82 0 top
C85  0.22u/6.3V_2  [C0201]  114.27 111.06 0 top
C86  0.22u/6.3V_2  [C0201]  113.25 110.55 0 top
C87  0.22u/6.3V_2  [C0201]  113.25 109.84 0 top
C88  0.22u/6.3V_2  [C0201]  114.27 109.28 0 top
C89  0.22u/6.3V_2  [C0201]  114.27 108.52 0 top
C90  0.22u/6.3V_2  [C0201]  113.25 108.01 0 top
C91  0.22u/6.3V_2  [C0201]  113.25 107.25 0 top
C92  0.1u/16V_4  [C0402]  103.4 102.78 90 top
C93  22u/6.3V_6  [C0603]  110.88 102.72 180 top
C94  10u/6.3V_6  [C0603]  107.18 100.7 270 top
C95  10u/6.3V_6  [C0603]  108.61 100.66 270 top
C96  22u/6.3V_6  [C0603]  110.06 100.66 270 top
C97  10u/6.3V_4  [C0402_2]  105.56 100.12 0 top
C98  10u/6.3V_4  [C0402_2]  105.56 98.85 0 top
C99  1u/6.3V_4  [C0402]  110.48 91.5 270 top
C100  0.1u/16V_4  [C0402]  13.2 71.01 0 top
C101  10u/6.3V_4  [C0402_2]  13.23 69.89 0 top
C102  1u/6.3V_4  [C0402]  96.37 68.6 0 top
C103  *1u/6.3V_4  [C0402]  99.37 65.82 270 top
C104  10u/6.3V_6  [C0603]  95.9 67.02 0 top
C105  10u/6.3V_6  [C0603]  95.89 65.6 0 top
C106  1u/6.3V_4  [C0402]  133.16 64.19 270 top
C107  1u/6.3V_4  [C0402]  134.23 64.19 270 top
C108  1u/6.3V_4  [C0402]  135.4 64.18 270 top
C109  1u/6.3V_4  [C0402]  131.66 64.14 270 top
C110  1u/6.3V_4  [C0402]  116.47 64.11 270 top
C111  1u/6.3V_4  [C0402]  117.54 64.11 270 top
C112  1u/6.3V_4  [C0402]  118.58 64.11 270 top
C113  1u/6.3V_4  [C0402]  115.38 64.08 270 top
C114  1u/6.3V_4  [C0402]  110.89 64.05 270 top
C115  1u/6.3V_4  [C0402]  119.78 64.05 270 top
C116  1u/6.3V_4  [C0402]  120.92 64.05 270 top
C117  1u/6.3V_4  [C0402]  122.07 64.05 270 top
C118  1u/6.3V_4  [C0402]  123.21 64.05 270 top
C119  1u/6.3V_4  [C0402]  124.35 64.05 270 top
C120  2.2u/10V_4  [C0402]  95.93 64.36 180 top
C121  0.1u/16V_4  [C0402]  98.44 63.32 90 top
C122  10u/6.3V_4  [C0402_2]  159.34 63.08 270 top
C123  10u/6.3V_4  [C0402_2]  160.53 63.08 270 top
C124  1u/6.3V_4  [C0402]  161.72 63.08 270 top
C125  1u/6.3V_4  [C0402]  147.95 63.04 270 top
C126  1u/6.3V_4  [C0402]  140.48 63.03 270 top
C127  1u/6.3V_4  [C0402]  141.75 63.03 270 top
C128  1u/6.3V_4  [C0402]  143.02 63.03 270 top
C129  1u/6.3V_4  [C0402]  144.29 63.03 270 top
C130  1u/6.3V_4  [C0402]  146.7 63.03 270 top
C131  0.1u/16V_4  [C0402]  149.12 63.03 90 top
C132  1u/6.3V_4  [C0402]  150.26 63.03 270 top
C133  1u/6.3V_4  [C0402]  151.4 63.03 270 top
C134  1u/6.3V_4  [C0402]  152.55 63.03 270 top
C135  1u/6.3V_4  [C0402]  153.69 63.03 270 top
C136  1u/6.3V_4  [C0402]  154.83 63.03 270 top
C137  1u/6.3V_4  [C0402]  155.97 63.03 270 top
C138  1u/6.3V_4  [C0402]  157.12 63.03 270 top
C139  1u/6.3V_4  [C0402]  158.26 63.03 270 top
C140  10u/6.3V_4  [C0402_2]  162.83 63.03 270 top
C141  1u/6.3V_4  [C0402]  165.12 63.03 270 top
C142  1u/6.3V_4  [C0402]  145.56 63.02 270 top
C143  2.2u/10V_4  [C0402]  99.42 63.32 90 top
C144  47u/6.3V_6  [C0603]  276.24 56.18 90 top
C145  47u/6.3V_6  [C0603]  277.77 56.18 90 top
C146  47u/6.3V_6  [C0603]  279.29 56.18 90 top
C147  10u/6.3V_4  [C0402_2]  191.6 55.86 270 top
C148  *47u/6.3V_8  [C0805]  197.12 55.84 0 top
C149  0.1u/10V_2  [C0201]  191.22 54.59 180 top
C150  10u/6.3V_4  [C0402_2]  197.12 54.25 180 top
C151  0.022u/25V_4  [C0402]  179 52.92 270 top
C152  0.1u/10V_2  [C0201]  49.93 52.52 90 top
C153  10u/6.3V_4  [C0402_2]  242.97 52.49 270 top
C154  0.1u/10V_2  [C0201]  243.99 52.49 90 top
C155  *1u/6.3V_2  [C0201]  244.75 52.49 90 top
C156  0.1u/10V_2  [C0201]  245.51 52.49 90 top
C157  1u/10V_4  [C0402]  278.15 52.37 0 top
C158  0.1u/10V_2  [C0201]  202.83 52.3 180 top
C159  10u/6.3V_4  [C0402_2]  48.91 52.11 270 top
C160  0.1u/10V_2  [C0201]  50.06 51.6 0 top
C161  0.1u/10V_2  [C0201]  194.46 51.35 180 top
C162  1u/6.3V_4  [C0402]  202.33 51.35 0 top
C163  1u/6.3V_4  [C0402]  199.75 51.03 90 top
C164  0.1u/10V_2  [C0201]  50.06 50.71 0 top
C165  0.1u/10V_2  [C0201]  194.46 50.59 180 top
C166  0.1u/10V_2  [C0201]  200.6 50.49 270 top
C167  0.1u/10V_2  [C0201]  239.16 50.33 0 top
C168  0.1u/10V_2  [C0201]  248.05 50.33 180 top
C169  0.1u/10V_2  [C0201]  50.06 49.98 180 top
C170  0.1u/10V_2  [C0201]  194.46 49.83 180 top
C171  0.22u/6.3V_2  [C0201]  227.8 49.7 0 top
C172  0.1u/10V_2  [C0201]  239.16 49.57 0 top
C173  0.1u/10V_2  [C0201]  248.05 49.57 180 top
C174  0.22u/6.3V_2  [C0201]  230.41 49.31 0 top
C175  0.1u/16V_4  [C0402]  180.46 49.28 0 top
C176  0.22u/6.3V_2  [C0201]  223.92 49.13 90 top
C177  0.22u/6.3V_2  [C0201]  224.69 49.13 90 top
C178  0.22u/6.3V_2  [C0201]  225.45 49.13 90 top
C179  0.22u/6.3V_2  [C0201]  226.21 49.13 90 top
C180  0.1u/10V_2  [C0201]  194.46 49.06 180 top
C181  0.22u/6.3V_2  [C0201]  227.8 48.93 0 top
C182  0.1u/10V_2  [C0201]  239.16 48.81 0 top
C183  0.1u/10V_2  [C0201]  248.05 48.81 180 top
C184  0.22u/6.3V_2  [C0201]  230.41 48.55 0 top
C185  0.22u/6.3V_2  [C0201]  270.96 48.23 180 top
C186  *2.2u/10V_6  [C0603]  180.82 48.08 180 top
C187  0.1u/10V_2  [C0201]  239.16 48.05 0 top
C188  0.1u/10V_2  [C0201]  248.05 48.05 180 top
C189  1u/6.3V_2  [C0201]  20.49 47.84 270 top
C190  0.22u/6.3V_2  [C0201]  270.96 47.46 180 top
C191  1u/6.3V_4  [C0402]  99.99 47.69 0 top
C192  1u/6.3V_4  [C0402]  230.45 47.33 270 top
C193  0.1u/10V_2  [C0201]  239.16 47.29 0 top
C194  0.1u/10V_2  [C0201]  248.05 47.29 180 top
C195  22u/6.3V_6  [C0603]  231.67 47.1 270 top
C196  22u/6.3V_6  [C0603]  233.09 47.1 90 top
C197  *2.2u/10V_6  [C0603]  180.82 46.48 180 top
C198  0.1u/10V_2  [C0201]  199.03 46.59 0 top
C199  0.1u/16V_4  [C0402]  12.19 46.57 90 top
C200  10u/6.3V_4  [C0402_2]  93.57 69.59 90 bottom
C201  0.1u/10V_2  [C0201]  239.16 46.52 0 top
C202  0.1u/10V_2  [C0201]  248.05 46.52 180 top
C203  0.1u/10V_2  [C0201]  239.16 45.76 0 top
C204  0.1u/10V_2  [C0201]  248.05 45.76 180 top
C205  1u/6.3V_4  [C0402]  199.34 45.72 180 top
C206  0.1u/10V_2  [C0201]  230.4 45.57 90 top
C207  0.1u/16V_4  [C0402]  180.38 44.95 180 top
C208  0.1u/10V_2  [C0201]  239.16 45 0 top
C209  0.1u/10V_2  [C0201]  248.05 45 180 top
C210  0.1u/16V_4  [C0402]  180.38 43.94 0 top
C211  0.1u/10V_2  [C0201]  239.16 44.24 180 top
C212  0.1u/16V_4  [C0402]  10.71 43.98 270 top
C213  10u/6.3V_4  [C0402_2]  11.86 43.98 270 top
C214  0.1u/10V_2  [C0201]  247.16 43.98 0 top
C215  0.22u/6.3V_2  [C0201]  260.11 43.22 270 top
C216  0.22u/6.3V_2  [C0201]  260.88 43.22 270 top
C217  0.22u/6.3V_2  [C0201]  261.64 43.22 270 top
C218  0.22u/6.3V_2  [C0201]  262.4 43.22 270 top
C219  0.22u/6.3V_2  [C0201]  263.16 43.22 270 top
C220  0.22u/6.3V_2  [C0201]  263.92 43.22 270 top
C221  0.22u/6.3V_2  [C0201]  264.66 43.22 270 top
C222  0.22u/6.3V_2  [C0201]  265.37 43.22 270 top
C223  10p/50V_4  [C0402]  266.6 43.19 180 top
C224  10p/50V_4  [C0402]  268.33 43.19 0 top
C225  0.1u/16V_4  [C0402]  99.05 42.59 270 top
C226  1u/6.3V_2  [C0201]  19.14 40.5 270 top
C227  10u/6.3V_4  [C0402_2]  12.34 41.21 0 top
C228  4.7u/6.3V_4  [C0402_2]  250.46 41.19 180 top
C229  *1u/6.3V_4  [C0402]  99.02 41.22 0 top
C230  0.1u/10V_2  [C0201]  245.38 41.06 180 top
C231  0.1u/16V_4  [C0402]  56.39 40.49 270 top
C232  0.1u/16V_4  [C0402]  57.4 40.49 270 top
C233  0.1u/10V_2  [C0201]  245.38 40.3 180 top
C234  0.1u/16V_4  [C0402]  12.34 40.1 0 top
C235  1u/6.3V_4  [C0402]  99.03 40.25 0 top
C236  0.1u/16V_4  [C0402]  179.87 39.73 0 top
C237  33p/50V_4  [C0402]  259.35 39.16 90 top
C238  0.1u/16V_4  [C0402]  260.37 39.16 270 top
C239  0.22u/10V_4  [C0402]  261.38 39.16 90 top
C240  0.22u/10V_4  [C0402]  262.4 39.16 90 top
C241  0.22u/10V_4  [C0402]  263.42 39.16 90 top
C242  0.22u/10V_4  [C0402]  264.43 39.16 90 top
C243  0.1u/16V_4  [C0402]  277.39 38.9 270 top
C244  10u/6.3V_6  [C0603]  99.63 38.76 0 top
C245  180p/50V_4  [C0402]  74.99 38.43 90 top
C246  0.1u/10V_2  [C0201]  63.22 37.79 270 top
C247  0.1u/16V_4  [C0402]  265.96 37.76 90 top
C248  10u/6.3V_4  [C0402_2]  267.28 37.76 90 top
C249  1000p/50V_4  [C0402]  268.6 37.76 90 top
C250  390p/50V_4  [C0402]  285.9 37.76 180 top
C251  0.1u/10V_2  [C0201]  74.01 37.58 90 top
C252  0.1u/10V_2  [C0201]  73.28 37.56 90 top
C253  180p/50V_4  [C0402]  83.49 37.51 90 top
C254  0.1u/10V_2  [C0201]  84.95 37.49 0 top
C255  10u/6.3V_6  [C0603]  99.61 37.33 0 top
C256  0.1u/10V_2  [C0201]  80.33 37.41 270 top
C257  22u/6.3V_6  [C0603]  254.53 37.38 270 top
C258  0.1u/10V_2  [C0201]  77.11 37.34 90 top
C259  180p/50V_4  [C0402]  67 37.01 0 top
C260  33p/50V_4  [C0402]  257.32 37.25 270 top
C261  0.1u/10V_2  [C0201]  34.56 37.15 0 top
C262  0.1u/10V_2  [C0201]  71.31 36.67 180 top
C263  33p/50V_4  [C0402]  32.48 36.64 90 top
C264  33p/50V_4  [C0402]  33.55 36.64 90 top
C265  0.1u/10V_2  [C0201]  29.45 36.5 90 top
C266  CNV@1u/6.3V_4  [C0402]  53.99 36.54 90 top
C267  10u/6.3V_4  [C0402_2]  30.42 36.49 270 top
C268  10u/6.3V_4  [C0402_2]  23.26 36.36 180 top
C269  *47u/6.3V_8  [C0805]  190.52 36.13 180 top
C270  390p/50V_4  [C0402]  285.9 36.36 180 top
C271  10u/6.3V_6  [C0603]  99.33 35.23 0 top
C272  10u/6.3V_4  [C0402_2]  34.64 35.88 270 top
C273  10u/6.3V_6  [C0603]  103.22 34.64 90 top
C274  10u/6.3V_6  [C0603]  104.64 34.69 90 top
C275  180p/50V_4  [C0402]  70.13 35.53 270 top
C276  *0.1u/10V_2  [C0201]  97.43 35.42 0 top
C277  22p/25V_2  [C0201]  29.1 35.25 90 top
C278  0.1u/10V_2  [C0201]  24.78 35.12 180 top
C279  10u/6.3V_4  [C0402_2]  30.32 35.02 0 top
C280  0.1u/10V_2  [C0201]  31.77 34.97 0 top
C281  1u/6.3V_4  [C0402]  99.01 33.78 0 top
C282  1u/6.3V_2  [C0201]  61.05 34.46 180 top
C283  *47u/6.3V_8  [C0805]  190.52 34.16 180 top
C284  *0.1u/16V_4  [C0402]  145.31 34.2 180 top
C285  0.1u/10V_2  [C0201]  34.64 34.1 90 top
C286  1u/6.3V_4  [C0402]  101.63 34.79 180 top
C287  10u/6.3V_4  [C0402_2]  36.85 33.85 180 top
C288  10u/6.3V_4  [C0402_2]  53.26 33.7 180 top
C289  *0.1u/10V_2  [C0201]  25.8 33.6 180 top
C290  10u/6.3V_6  [C0603]  101.18 33.58 180 top
C291  10u/6.3V_6  [C0603]  150.38 33.45 90 top
C292  10u/6.3V_6  [C0603]  137.46 33.45 90 top
C293  10u/6.3V_6  [C0603]  115.97 33.44 90 top
C294  10u/6.3V_6  [C0603]  117.49 33.44 90 top
C295  10u/6.3V_6  [C0603]  123.34 33.44 90 top
C296  10u/6.3V_6  [C0603]  124.86 33.44 90 top
C297  10u/6.3V_6  [C0603]  126.38 33.44 90 top
C298  10u/6.3V_6  [C0603]  131.34 33.44 90 top
C299  10u/6.3V_6  [C0603]  132.86 33.44 90 top
C300  10u/6.3V_6  [C0603]  134.38 33.44 90 top
C301  10u/6.3V_6  [C0603]  142.13 33.44 90 top
C302  10u/6.3V_6  [C0603]  143.66 33.44 90 top
C303  22u/6.3V_6  [C0603]  148.86 33.44 90 top
C304  10u/6.3V_6  [C0603]  151.86 33.44 90 top
C305  10u/6.3V_6  [C0603]  156.23 33.44 90 top
C306  10u/6.3V_6  [C0603]  157.75 33.44 90 top
C307  10u/6.3V_6  [C0603]  159.28 33.44 90 top
C308  10u/6.3V_6  [C0603]  160.8 33.44 90 top
C309  10u/6.3V_6  [C0603]  162.32 33.44 90 top
C310  10u/6.3V_6  [C0603]  163.98 33.44 90 top
C311  10u/6.3V_6  [C0603]  165.5 33.44 90 top
C312  1u/6.3V_4  [C0402]  256.69 33.44 180 top
C313  10u/6.3V_6  [C0603]  135.93 33.43 90 top
C314  10u/6.3V_6  [C0603]  153.3 33.43 90 top
C315  10u/6.3V_6  [C0603]  154.75 33.43 90 top
C316  10u/6.3V_6  [C0603]  119.01 33.42 90 top
C317  10u/6.3V_6  [C0603]  120.43 33.42 90 top
C318  10u/6.3V_6  [C0603]  121.88 33.4 90 top
C319  *0.1u/16V_4  [C0402]  145.34 33.24 180 top
C320  0.1u/16V_4  [C0402]  238.14 33.21 180 top
C321  0.1u/10V_2  [C0201]  26.05 32.71 90 top
C322  *0.1u/16V_4  [C0402]  147.18 32.45 0 top
C323  *0.1u/16V_4  [C0402]  145.34 32.25 180 top
C324  1u/6.3V_2  [C0201]  53.85 31.47 90 top
C325  0.1u/10V_2  [C0201]  54.56 31.47 90 top
C326  0.01u/16V_2  [C0201]  55.27 31.47 90 top
C327  2.2u/10V_4  [C0402]  56 32.49 180 top
C328  1u/10V_4  [C0402]  238.14 32.25 0 top
C329  0.1u/10V_2  [C0201]  66.77 32.04 180 top
C330  2.2u/10V_4  [C0402]  97.06 31.95 0 top
C331  10u/6.3V_4  [C0402_2]  36.85 31.54 180 top
C332  0.1u/10V_2  [C0201]  87.27 31.54 270 top
C333  0.1u/10V_2  [C0201]  88.03 31.54 270 top
C334  0.1u/10V_2  [C0201]  66.79 31.32 180 top
C335  0.1u/16V_4  [C0402]  97.07 30.98 0 top
C336  0.1u/16V_4  [C0402]  37.92 30.41 180 top
C337  0.1u/16V_4  [C0402]  279.67 30.17 180 top
C338  10u/6.3V_4  [C0402_2]  24.02 30.14 180 top
C339  0.22u/25V_2  [C0201]  62.76 29.58 180 top
C340  4.7u/6.3V_4  [C0402_2]  264.81 29.63 90 top
C341  1000p/50V_4  [C0402]  265.96 29.63 270 top
C342  1u/6.3V_4  [C0402]  279.67 29.15 0 top
C343  0.1u/10V_2  [C0201]  24.02 29.12 0 top
C344  180p/50V_4  [C0402]  87.52 29.12 0 top
C345  10u/6.3V_4  [C0402_2]  189.63 29.12 0 top
C346  10u/6.3V_6  [C0603]  247.9 29 90 top
C347  10u/6.3V_6  [C0603]  249.32 29 90 top
C348  680p/50V_4  [C0402]  50.82 28.9 180 top
C349  10u/6.3V_6  [C0603]  250.87 28.77 90 top
C350  0.22u/25V_2  [C0201]  62.76 28.87 180 top
C351  1000p/50V_4  [C0402]  271.8 28.13 270 top
C352  10u/6.3V_4  [C0402_2]  24.02 28.11 0 top
C353  *180p/50V_4  [C0402]  89.3 28.11 0 top
C354  0.1u/10V_2  [C0201]  189.76 28.11 180 top
C355  2.2u/10V_6  [C0603]  37.1 27.88 0 top
C356  680p/50V_4  [C0402]  50.67 27.68 180 top
C357  0.22u/25V_2  [C0201]  62.76 27.09 180 top
C358  2.2u/10V_4  [C0402]  40.25 27.22 180 top
C359  680p/50V_4  [C0402]  7.05 26.97 270 top
C360  0.1u/16V_4  [C0402]  24.02 26.97 0 top
C361  1u/6.3V_4  [C0402]  36.59 26.46 0 top
C362  0.1u/16V_4  [C0402]  48.28 26.46 180 top
C363  10u/6.3V_4  [C0402_2]  50.82 26.46 180 top
C364  0.22u/25V_2  [C0201]  62.76 26.38 180 top
C365  18p/50V_4  [C0402]  231.67 26.4 90 top
C366  0.33u/6.3V_4  [C0402]  40.4 25.95 0 top
C367  0.1u/16V_4  [C0402]  249.95 25.95 90 top
C368  1u/6.3V_4  [C0402]  251.22 25.95 270 top
C369  1u/6.3V_4  [C0402]  252.24 25.95 270 top
C370  10u/6.3V_4  [C0402_2]  24 25.87 180 top
C371  0.1u/16V_4  [C0402]  26.26 25.59 180 top
C372  0.33u/6.3V_4  [C0402]  267.18 25.51 90 top
C373  0.33u/6.3V_4  [C0402]  268.19 25.51 90 top
C374  0.22u/10V_4  [C0402]  265.09 25.47 90 top
C375  0.22u/10V_4  [C0402]  266.11 25.47 90 top
C376  *47u/6.3V_8  [C0805]  192.04 25.44 180 top
C377  0.33u/6.3V_4  [C0402]  261 25.44 90 top
C378  0.33u/6.3V_4  [C0402]  262.02 25.44 90 top
C379  0.22u/10V_4  [C0402]  263.04 25.44 90 top
C380  0.22u/10V_4  [C0402]  264.05 25.44 90 top
C381  1u/6.3V_4  [C0402]  36.59 25.31 0 top
C382  0.22u/25V_2  [C0201]  62.76 24.96 180 top
C383  33p/50V_4  [C0402]  257.83 25.31 180 top
C384  1000p/50V_4  [C0402]  269.92 25.31 0 top
C385  1u/6.3V_4  [C0402]  21.99 25.21 180 top
C386  *1u/6.3V_4  [C0402]  253.76 25.19 180 top
C387  680p/50V_4  [C0402]  7.05 25.06 90 top
C388  0.33u/6.3V_4  [C0402]  16.78 24.81 180 top
C389  0.33u/6.3V_4  [C0402]  40.4 24.81 0 top
C390  680p/50V_4  [C0402]  50.46 24.63 180 top
C391  18p/50V_4  [C0402]  231.67 24.62 270 top
C392  0.1u/10V_2  [C0201]  86.53 24.49 90 top
C393  *0.1u/10V_2  [C0201]  90.82 23.79 270 top
C394  0.1u/16V_4  [C0402]  269.92 24.35 0 top
C395  33p/50V_4  [C0402]  259.61 24.3 0 top
C396  10u/6.3V_4  [C0402_2]  24.73 24.22 180 top
C397  0.22u/25V_2  [C0201]  62.76 24.25 180 top
C398  2.2u/10V_6  [C0603]  35.02 24.07 180 top
C399  1u/6.3V_4  [C0402]  21.99 24.04 180 top
C400  0.1u/16V_4  [C0402]  9.24 23.99 0 top
C401  0.33u/6.3V_4  [C0402]  16.78 23.66 180 top
C402  10u/6.3V_4  [C0402_2]  7.51 23.54 0 top
C403  10u/6.3V_4  [C0402_2]  192.04 23.54 0 top
C404  180p/50V_4  [C0402]  87.57 23.31 180 top
C405  10u/6.3V_4  [C0402_2]  269.92 23.26 0 top
C406  0.22u/25V_2  [C0201]  62.76 22.77 180 top
C407  *0.1u/16V_4  [C0402]  233.55 22.84 180 top
C408  680p/50V_4  [C0402]  50.92 22.64 180 top
C409  2.2u/10V_4  [C0402]  16.78 22.52 0 top
C410  0.1u/10V_2  [C0201]  193.31 22.52 270 top
C411  0.1u/10V_2  [C0201]  194.07 22.52 270 top
C412  0.1u/10V_2  [C0201]  194.84 22.52 270 top
C413  0.1u/10V_2  [C0201]  195.6 22.52 270 top
C414  0.1u/16V_4  [C0402]  257.45 22.52 0 top
C415  0.1u/10V_2  [C0201]  66.49 22.17 180 top
C416  680p/50V_4  [C0402]  7.13 22.01 270 top
C417  0.33u/6.3V_4  [C0402]  22.1 22.01 270 top
C418  0.33u/6.3V_4  [C0402]  23.06 22.01 270 top
C419  2.2u/10V_4  [C0402]  24.02 22.01 90 top
C420  10u/6.3V_4  [C0402_2]  35.3 22.01 90 top
C421  0.1u/16V_4  [C0402]  36.37 22.01 90 top
C422  10u/6.3V_4  [C0402_2]  87.52 21.99 0 top
C423  0.22u/25V_2  [C0201]  62.76 22.01 180 top
C424  100u/25V_D6.3H5.8  [ECAP6_3X5_8-7_2-2P]  29.8 21.53 0 top
C425  0.1u/16V_4  [C0402]  257.45 21.5 0 top
C426  180p/50V_4  [C0402]  87.52 20.9 180 top
C427  0.01u/16V_2  [C0201]  61.11 20.87 0 top
C428  0.1u/16V_4  [C0402]  246.14 20.74 180 top
C429  0.1u/16V_4  [C0402]  257.45 20.49 0 top
C430  *1000p/50V_4  [C0402]  89.58 20.48 0 top
C431  0.1u/16V_4  [C0402]  233.32 20.43 0 top
C432  1u/6.3V_4  [C0402]  230.95 20.26 270 top
C433  0.1u/16V_4  [C0402]  231.91 20.26 270 top
C434  680p/50V_4  [C0402]  7.13 20.11 90 top
C435  *0.1u/16V_4  [C0402]  46.12 19.98 270 top
C436  0.1u/16V_4  [C0402]  228.72 19.97 0 top
C437  *0.1u/16V_4  [C0402]  246.14 19.73 180 top
C438  0.1u/16V_4  [C0402]  234.7 19.6 90 top
C439  470p/50V_4  [C0402]  284.12 19.57 0 top
C440  0.01u/16V_2  [C0201]  61.11 19.57 0 top
C441  *0.1u/16V_4  [C0402]  220.47 19.44 90 top
C442  *47p/50V_4  [C0402]  203.35 19.42 270 top
C443  *1000p/50V_4  [C0402]  88.23 19.37 270 top
C444  *0.1u/16V_4  [C0402]  254.91 19.22 0 top
C445  0.1u/16V_4  [C0402]  228.72 19.01 0 top
C446  0.1u/16V_4  [C0402]  96.92 19.22 180 top
C447  0.1u/16V_4  [C0402]  65.3 18.76 180 top
C448  0.1u/16V_4  [C0402]  284.13 18.58 0 top
C449  0.1u/10V_2  [C0201]  61.11 18.86 0 top
C450  0.1u/16V_4  [C0402]  230.4 18.32 90 top
C451  *10u/6.3V_4  [C0402_2]  67.28 18.25 0 top
C452  1u/6.3V_4  [C0402]  228.75 18.04 180 top
C453  10u/6.3V_4  [C0402_2]  48.74 17.82 270 top
C454  0.1u/16V_4  [C0402]  284.12 17.59 0 top
C455  1000p/50V_4  [C0402]  257.45 17.44 180 top
C456  *0.1u/16V_4  [C0402]  253.26 17.19 270 top
C457  *HDD@47u/6.3V_8  [C0805]  38.32 17.03 270 top
C458  *HDD@47u/6.3V_8  [C0805]  40.35 17.03 270 top
C459  0.1u/16V_4  [C0402]  29.45 15.14 0 top
C460  10u/6.3V_4  [C0402_2]  29.33 16.62 0 top
C461  680p/50V_4  [C0402]  16.27 16.42 0 top
C462  0.1u/16V_4  [C0402]  244.75 15.75 180 top
C463  0.1u/10V_2  [C0201]  11.52 15.28 90 top
C464  HDD@10u/6.3V_6  [C0603]  35.2 15.28 90 top
C465  4.7u/6.3V_4  [C0402_2]  269.13 15.28 180 top
C466  680p/50V_4  [C0402]  26.79 15.08 90 top
C467  *HDD@0.1u/16V_4  [C0402]  31.9 15.03 90 top
C468  *HDD@0.1u/16V_4  [C0402]  32.91 15.03 90 top
C469  HDD@0.01u/50V_4  [C0402]  33.93 15.03 90 top
C470  1u/6.3V_4  [C0402]  250.31 14.88 90 top
C471  680p/50V_4  [C0402]  21.04 14.8 90 top
C472  1u/6.3V_4  [C0402]  244.75 14.78 0 top
C473  680p/50V_4  [C0402]  16.27 14.77 0 top
C474  100u/6.3V_12  [C1206]  282.57 14.77 180 top
C475  0.22u/25V_2  [C0201]  271.85 14.33 0 top
C476  1u/6.3V_4  [C0402]  201.44 14.57 180 top
C477  18p/50V_4  [C0402]  257.07 14.01 90 top
C478  0.22u/25V_2  [C0201]  271.85 13.6 0 top
C479  0.22u/25V_2  [C0201]  280.56 13.25 0 top
C480  0.22u/10V_4  [C0402]  261.13 12.61 90 top
C481  0.22u/10V_4  [C0402]  262.15 12.61 90 top
C482  0.22u/10V_4  [C0402]  263.16 12.61 90 top
C483  0.22u/10V_4  [C0402]  264.18 12.61 90 top
C484  1u/6.3V_4  [C0402]  267.99 12.61 270 top
C485  *47u/6.3V_8  [C0805]  190.14 12.49 180 top
C486  0.22u/25V_2  [C0201]  280.56 12.49 0 top
C487  0.33u/6.3V_4  [C0402]  258.72 11.85 270 top
C488  1u/6.3V_4  [C0402]  202.91 11.34 270 top
C489  1u/6.3V_4  [C0402]  205 11.34 90 top
C490  0.22u/25V_2  [C0201]  272.13 10.86 0 top
C491  *47u/6.3V_8  [C0805]  190.14 10.46 180 top
C492  0.1u/16V_4  [C0402]  206.22 9.95 270 top
C493  1u/6.3V_4  [C0402]  257.65 9.59 180 top
C494  0.22u/25V_2  [C0201]  272.13 10.15 0 top
C495  2.2u/10V_4  [C0402]  283.33 7.03 180 top
C496  0.1u/16V_4  [C0402]  25.55 169.46 270 bottom
C497  10u/6.3V_4  [C0402_2]  24.81 167.86 0 bottom
C498  0.1u/16V_4  [C0402]  44.75 165.96 0 bottom
C499  0.1u/16V_4  [C0402]  44.75 164.94 0 bottom
C500  0.1u/10V_2  [C0201]  97.25 164.79 270 bottom
C501  *3.3p/50V_4  [C0402]  61.85 164.75 90 bottom
C502  *220p/50V_4  [C0402]  71.65 164 180 bottom
C503  0.1u/16V_4  [C0402]  46.63 164.43 0 bottom
C504  0.1u/16V_4  [C0402]  46.63 163.41 0 bottom
C505  0.1u/16V_4  [C0402]  44.7 163.02 0 bottom
C506  0.1u/16V_4  [C0402]  44.7 162.01 0 bottom
C507  0.1u/16V_4  [C0402]  46.63 161.33 0 bottom
C508  0.01u/50V_4  [C0402]  76.6 160.93 270 bottom
C509  220p/50V_4  [C0402]  81.71 160.32 0 bottom
C510  0.1u/16V_4  [C0402]  46.63 160.32 0 bottom
C511  0.1u/10V_2  [C0201]  100.32 160.01 180 bottom
C512  0.1u/10V_2  [C0201]  80.03 159.96 90 bottom
C513  10u/6.3V_4  [C0402_2]  33.85 159.4 180 bottom
C514  180p/50V_4  [C0402]  43.58 159.84 180 bottom
C515  0.1u/16V_4  [C0402]  57.45 159.45 270 bottom
C516  10u/6.3V_6  [C0603]  59.33 159.2 180 bottom
C517  10u/6.3V_4  [C0402_2]  29.93 159.14 90 bottom
C518  0.1u/16V_4  [C0402]  28.85 159.14 90 bottom
C519  *2200p/50V_4  [C0402]  23.34 159.05 90 bottom
C520  0.1u/16V_4  [C0402]  33.67 157.9 90 bottom
C521  0.1u/10V_2  [C0201]  80.03 158.82 90 bottom
C522  0.01u/50V_4  [C0402]  76.6 158.44 90 bottom
C523  10u/6.3V_4  [C0402_2]  35.83 157.93 90 bottom
C524  0.1u/16V_4  [C0402]  34.69 157.93 90 bottom
C525  1u/6.3V_4  [C0402]  48.28 157.9 270 bottom
C526  10u/6.3V_4  [C0402_2]  95.9 156.53 270 bottom
C527  0.1u/10V_2  [C0201]  96.45 151.19 270 bottom
C528  0.1u/10V_2  [C0201]  96.28 148.25 90 bottom
C529  0.1u/10V_2  [C0201]  95.52 148.25 90 bottom
C530  0.1u/10V_2  [C0201]  94.76 148.25 90 bottom
C531  0.1u/10V_2  [C0201]  94 148.25 90 bottom
C532  0.1u/10V_2  [C0201]  93.24 148.25 90 bottom
C533  0.1u/10V_2  [C0201]  92.47 148.25 90 bottom
C534  0.1u/10V_2  [C0201]  91.71 148.25 90 bottom
C535  0.1u/10V_2  [C0201]  90.95 148.25 90 bottom
C536  22u/25V_8  [C0805]  173.12 136.44 0 bottom
C537  22u/6.3V_6  [C0603]  109.63 135.13 180 bottom
C538  100p/50V_4  [C0402]  172.36 134.92 0 bottom
C539  0.1u/10V_2  [C0201]  174.21 133.8 180 bottom
C540  1u/10V_2  [C0201]  129.74 129.63 180 bottom
